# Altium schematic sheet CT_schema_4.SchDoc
size 368 x 245 mm
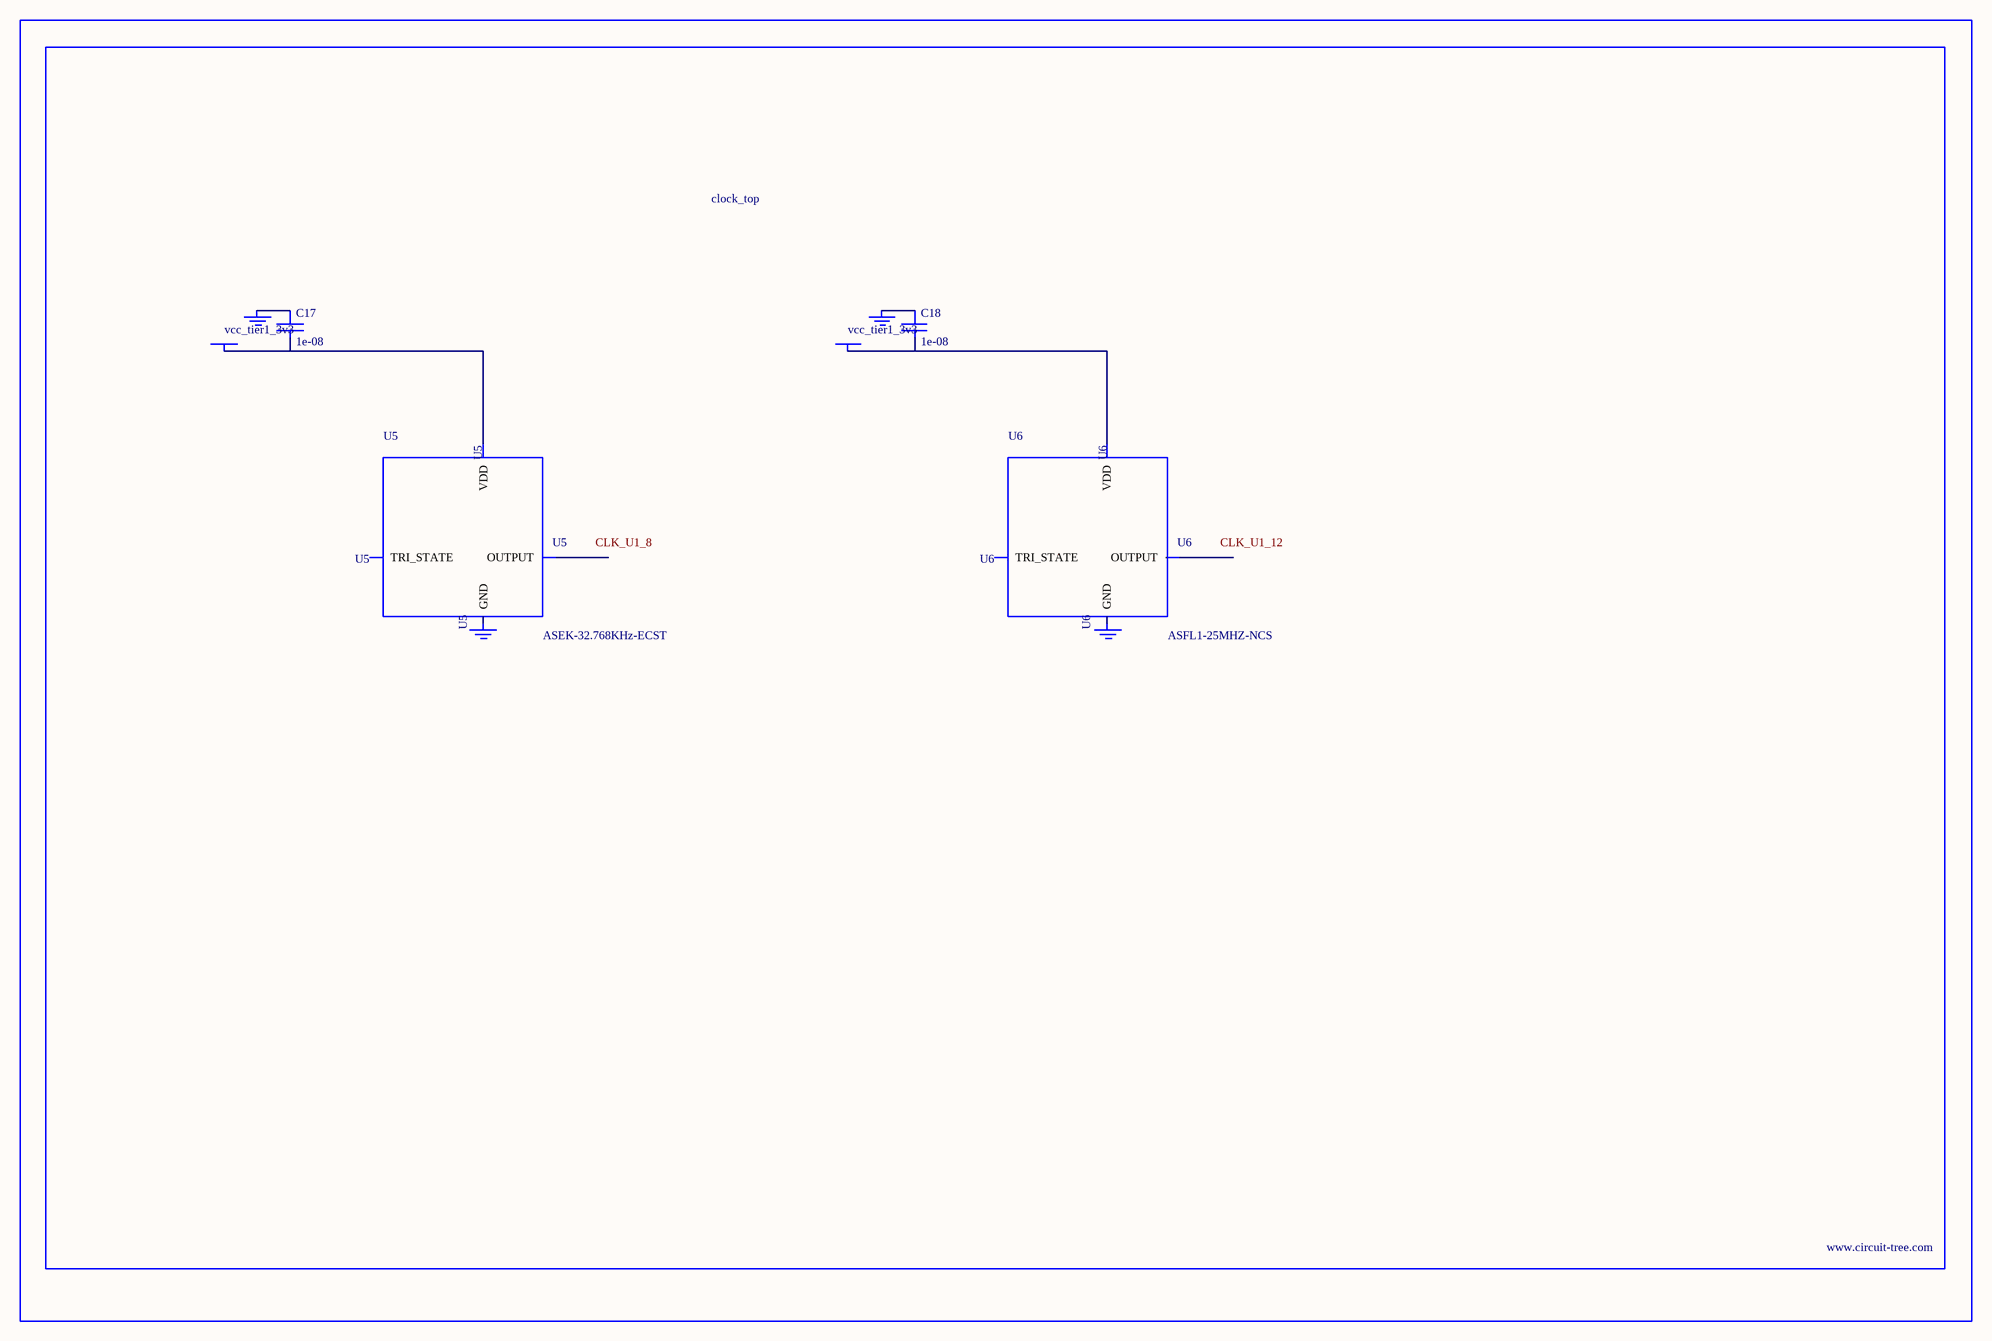
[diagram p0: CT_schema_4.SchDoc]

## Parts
BORDER3  (no value)
C17  1e-08  [C0402]
C18  1e-08  [C0402]
GND_INSTANCE_3_0  (no value)
GND_INSTANCE_3_1  (no value)
GND_INSTANCE_3_2  (no value)
GND_INSTANCE_3_3  (no value)
POWER_INSTANCE_3_0  vcc_tier1_3v3
POWER_INSTANCE_3_1  vcc_tier1_3v3
U5  ASEK-32.768KHz-ECST  [ASEK]
U6  ASFL1-25MHZ-NCS  [ASFL1]

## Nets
NetC17_1: C17.1 GND_INSTANCE_3_0.0(GND)
NetC17_2: C17.2 POWER_INSTANCE_3_0.0(PWR) U5.4(VDD)
NetC18_1: C18.1 GND_INSTANCE_3_2.0(GND)
NetC18_2: C18.2 POWER_INSTANCE_3_1.0(PWR) U6.4(VDD)

Not connected (* = marked no-connect by the designer): GND_INSTANCE_3_1 0(GND); GND_INSTANCE_3_3 0(GND); U5 1(TRI_STATE) 2(GND) 3(OUTPUT); U6 1(TRI_STATE) 2(GND) 3(OUTPUT)

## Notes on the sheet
- Labels drawn without touching a wire or pin: CLK_U1_8, CLK_U1_12

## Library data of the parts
BORDER3 = BORDER_PAGE3
C17 C18 = C0402C103K3RAC
GND_INSTANCE_3_0-GND_INSTANCE_3_3 = GND
POWER_INSTANCE_3_0 POWER_INSTANCE_3_1 = PWR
